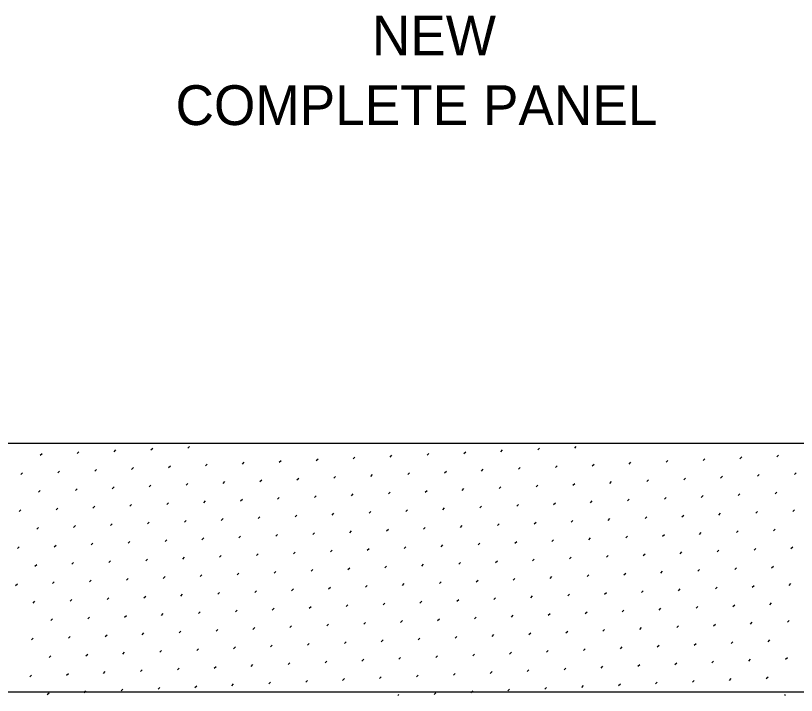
# Model space of a CAD drawing. Extents: x 49991.4 to 50021, y 49987.6 to 50011.4.
# Drawn here: x 50006.156 to 50007.726, y 49994.284 to 49995.65 of the extents above; entities that cross this region are included whole.
import ezdxf

# ---------------------------------------------------------------- set-up
doc = ezdxf.new("R2010")
doc.units = 0
for name, color, linetype in [('Level 1', 7, 'Continuous'), ('Level 10', 7, 'Continuous'), ('Level 2', 7, 'Continuous')]:
    doc.layers.add(name, color=color, linetype=linetype)

msp = doc.modelspace()

# ---------------------------------------------------------------- linework, layer by layer
at = {"layer": 'Level 1'}
for p, q in [((50007.9348, 49994.7903), (50002.3098, 49994.7903)), ((50015.1301, 49994.2903), (50001.3364, 49994.2903))]:
    msp.add_line(p, q, dxfattribs=at)
at = {"layer": 'Level 10'}
for p, q in [((50006.3541, 49994.7736), (50006.3576, 49994.7771)), ((50006.4283, 49994.7771), (50006.4319, 49994.7806)), ((50006.5026, 49994.7806), (50006.5058, 49994.7838)), ((50007.132, 49994.7736), (50007.1355, 49994.7772)), ((50007.2062, 49994.7772), (50007.2097, 49994.7807)), ((50007.2805, 49994.7807), (50007.2836, 49994.7838)), ((50006.2056, 49994.7665), (50006.2091, 49994.77)), ((50006.2798, 49994.77), (50006.2834, 49994.7735)), ((50006.8349, 49994.7595), (50006.8385, 49994.763)), ((50006.9092, 49994.763), (50006.9127, 49994.7665)), ((50006.9835, 49994.7665), (50006.987, 49994.7701)), ((50007.0577, 49994.7701), (50007.0612, 49994.7736)), ((50007.6128, 49994.7595), (50007.6164, 49994.7631)), ((50007.6871, 49994.7631), (50007.6906, 49994.7666)), ((50006.4637, 49994.7417), (50006.4672, 49994.7453)), ((50006.5379, 49994.7453), (50006.5415, 49994.7488)), ((50006.6122, 49994.7488), (50006.6157, 49994.7524)), ((50006.6864, 49994.7524), (50006.69, 49994.7559)), ((50006.7607, 49994.7559), (50006.7642, 49994.7594)), ((50007.2416, 49994.7418), (50007.2451, 49994.7453)), ((50007.3158, 49994.7454), (50007.3194, 49994.7489)), ((50007.3901, 49994.7489), (50007.3936, 49994.7524)), ((50007.4643, 49994.7524), (50007.4679, 49994.756)), ((50007.5386, 49994.756), (50007.5421, 49994.7595)), ((50006.1667, 49994.7276), (50006.1702, 49994.7311)), ((50006.2409, 49994.7311), (50006.2445, 49994.7347)), ((50006.3152, 49994.7347), (50006.3187, 49994.7382)), ((50006.3894, 49994.7382), (50006.393, 49994.7417)), ((50006.9446, 49994.7276), (50006.9481, 49994.7312)), ((50007.0188, 49994.7312), (50007.0223, 49994.7347)), ((50007.0931, 49994.7347), (50007.0966, 49994.7383)), ((50007.1673, 49994.7383), (50007.1709, 49994.7418)), ((50007.7224, 49994.7277), (50007.726, 49994.7312)), ((50006.5733, 49994.7099), (50006.5768, 49994.7135)), ((50006.6475, 49994.7135), (50006.6511, 49994.717)), ((50006.7218, 49994.717), (50006.7253, 49994.7206)), ((50006.796, 49994.7206), (50006.7996, 49994.7241)), ((50006.8703, 49994.7241), (50006.8738, 49994.7276)), ((50007.3512, 49994.71), (50007.3547, 49994.7135)), ((50007.4254, 49994.7135), (50007.429, 49994.7171)), ((50007.4997, 49994.7171), (50007.5032, 49994.7206)), ((50007.5739, 49994.7206), (50007.5775, 49994.7242)), ((50007.6482, 49994.7242), (50007.6517, 49994.7277)), ((50006.2763, 49994.6958), (50006.2798, 49994.6993)), ((50006.3505, 49994.6993), (50006.3541, 49994.7028)), ((50006.4248, 49994.7028), (50006.4283, 49994.7064)), ((50006.499, 49994.7064), (50006.5026, 49994.7099)), ((50007.0542, 49994.6958), (50007.0577, 49994.6994)), ((50007.1284, 49994.6994), (50007.132, 49994.7029)), ((50007.2027, 49994.7029), (50007.2062, 49994.7065)), ((50007.2769, 49994.7065), (50007.2805, 49994.71)), ((50006.202, 49994.6922), (50006.2056, 49994.6958)), ((50006.6829, 49994.6781), (50006.6864, 49994.6817)), ((50006.7572, 49994.6817), (50006.7607, 49994.6852)), ((50006.8314, 49994.6852), (50006.8349, 49994.6887)), ((50006.9057, 49994.6887), (50006.9092, 49994.6923)), ((50006.9799, 49994.6923), (50006.9834, 49994.6958)), ((50007.4608, 49994.6782), (50007.4643, 49994.6817)), ((50007.535, 49994.6817), (50007.5386, 49994.6853)), ((50007.6093, 49994.6853), (50007.6128, 49994.6888)), ((50007.6835, 49994.6888), (50007.6871, 49994.6924)), ((50006.3859, 49994.6639), (50006.3894, 49994.6675)), ((50006.4601, 49994.6675), (50006.4637, 49994.671)), ((50006.5344, 49994.671), (50006.5379, 49994.6746)), ((50006.6086, 49994.6746), (50006.6122, 49994.6781)), ((50007.1638, 49994.664), (50007.1673, 49994.6676)), ((50007.238, 49994.6676), (50007.2416, 49994.6711)), ((50007.3123, 49994.6711), (50007.3158, 49994.6746)), ((50007.3865, 49994.6746), (50007.3901, 49994.6782)), ((50006.1631, 49994.6533), (50006.1667, 49994.6569)), ((50006.2374, 49994.6569), (50006.2409, 49994.6604)), ((50006.3116, 49994.6604), (50006.3152, 49994.6639)), ((50006.8668, 49994.6498), (50006.8703, 49994.6534)), ((50006.941, 49994.6534), (50006.9445, 49994.6569)), ((50007.0153, 49994.6569), (50007.0188, 49994.6605)), ((50007.0895, 49994.6605), (50007.0931, 49994.664)), ((50007.6446, 49994.6499), (50007.6482, 49994.6535)), ((50007.7189, 49994.6535), (50007.7224, 49994.657)), ((50006.4955, 49994.6321), (50006.499, 49994.6357)), ((50006.5697, 49994.6357), (50006.5733, 49994.6392)), ((50006.644, 49994.6392), (50006.6475, 49994.6428)), ((50006.7183, 49994.6428), (50006.7218, 49994.6463)), ((50006.7925, 49994.6463), (50006.796, 49994.6498)), ((50007.2734, 49994.6322), (50007.2769, 49994.6357)), ((50007.3476, 49994.6357), (50007.3512, 49994.6393)), ((50007.4219, 49994.6393), (50007.4254, 49994.6428)), ((50007.4961, 49994.6428), (50007.4997, 49994.6464)), ((50007.5704, 49994.6464), (50007.5739, 49994.6499)), ((50006.1985, 49994.618), (50006.202, 49994.6215)), ((50006.2727, 49994.6215), (50006.2763, 49994.625)), ((50006.347, 49994.625), (50006.3505, 49994.6286)), ((50006.4212, 49994.6286), (50006.4248, 49994.6321)), ((50006.9764, 49994.618), (50006.9799, 49994.6216)), ((50007.0506, 49994.6216), (50007.0542, 49994.6251)), ((50007.1249, 49994.6251), (50007.1284, 49994.6287)), ((50007.1991, 49994.6287), (50007.2027, 49994.6322)), ((50006.6051, 49994.6003), (50006.6086, 49994.6039)), ((50006.6794, 49994.6039), (50006.6829, 49994.6074)), ((50006.7536, 49994.6074), (50006.7571, 49994.6109)), ((50006.8279, 49994.6109), (50006.8314, 49994.6145)), ((50006.9021, 49994.6145), (50006.9057, 49994.618)), ((50007.383, 49994.6004), (50007.3865, 49994.6039)), ((50007.4572, 49994.6039), (50007.4608, 49994.6075)), ((50007.5315, 49994.6075), (50007.535, 49994.611)), ((50007.6057, 49994.611), (50007.6093, 49994.6146)), ((50007.68, 49994.6146), (50007.6835, 49994.6181)), ((50006.3081, 49994.5862), (50006.3116, 49994.5897)), ((50006.3823, 49994.5897), (50006.3859, 49994.5932)), ((50006.4566, 49994.5932), (50006.4601, 49994.5968)), ((50006.5308, 49994.5968), (50006.5344, 49994.6003)), ((50007.086, 49994.5862), (50007.0895, 49994.5898)), ((50007.1602, 49994.5898), (50007.1638, 49994.5933)), ((50007.2345, 49994.5933), (50007.238, 49994.5968)), ((50007.3087, 49994.5968), (50007.3123, 49994.6004)), ((50006.1596, 49994.5791), (50006.1631, 49994.5826)), ((50006.2338, 49994.5826), (50006.2374, 49994.5861)), ((50006.7147, 49994.5685), (50006.7182, 49994.572)), ((50006.789, 49994.5721), (50006.7925, 49994.5756)), ((50006.8632, 49994.5756), (50006.8668, 49994.5791)), ((50006.9375, 49994.5791), (50006.941, 49994.5827)), ((50007.0117, 49994.5827), (50007.0153, 49994.5862)), ((50007.4926, 49994.5686), (50007.4961, 49994.5721)), ((50007.5669, 49994.5721), (50007.5704, 49994.5757)), ((50007.6411, 49994.5757), (50007.6446, 49994.5792)), ((50007.7154, 49994.5792), (50007.7189, 49994.5827)), ((50006.4177, 49994.5543), (50006.4212, 49994.5579)), ((50006.492, 49994.5579), (50006.4955, 49994.5614)), ((50006.5662, 49994.5614), (50006.5697, 49994.565)), ((50006.6405, 49994.565), (50006.644, 49994.5685)), ((50007.1956, 49994.5544), (50007.1991, 49994.5579)), ((50007.2698, 49994.558), (50007.2734, 49994.5615)), ((50007.3441, 49994.5615), (50007.3476, 49994.565)), ((50007.4183, 49994.565), (50007.4219, 49994.5686)), ((50006.1949, 49994.5437), (50006.1985, 49994.5472)), ((50006.2692, 49994.5473), (50006.2727, 49994.5508)), ((50006.3434, 49994.5508), (50006.347, 49994.5543)), ((50006.8986, 49994.5402), (50006.9021, 49994.5438)), ((50006.9728, 49994.5438), (50006.9764, 49994.5473)), ((50007.0471, 49994.5473), (50007.0506, 49994.5509)), ((50007.1213, 49994.5509), (50007.1249, 49994.5544)), ((50007.6765, 49994.5403), (50007.68, 49994.5438)), ((50006.5273, 49994.5225), (50006.5308, 49994.5261)), ((50006.6016, 49994.5261), (50006.6051, 49994.5296)), ((50006.6758, 49994.5296), (50006.6793, 49994.5331)), ((50006.7501, 49994.5332), (50006.7536, 49994.5367)), ((50006.8243, 49994.5367), (50006.8279, 49994.5402)), ((50007.3052, 49994.5226), (50007.3087, 49994.5261)), ((50007.3794, 49994.5261), (50007.383, 49994.5297)), ((50007.4537, 49994.5297), (50007.4572, 49994.5332)), ((50007.528, 49994.5332), (50007.5315, 49994.5368)), ((50007.6022, 49994.5368), (50007.6057, 49994.5403)), ((50006.2303, 49994.5084), (50006.2338, 49994.5119)), ((50006.3045, 49994.5119), (50006.3081, 49994.5154)), ((50006.3788, 49994.5154), (50006.3823, 49994.519)), ((50006.4531, 49994.519), (50006.4566, 49994.5225)), ((50007.0082, 49994.5084), (50007.0117, 49994.512)), ((50007.0824, 49994.512), (50007.086, 49994.5155)), ((50007.1567, 49994.5155), (50007.1602, 49994.519)), ((50007.2309, 49994.5191), (50007.2345, 49994.5226)), ((50006.156, 49994.5048), (50006.1596, 49994.5083)), ((50006.6369, 49994.4907), (50006.6404, 49994.4942)), ((50006.7112, 49994.4943), (50006.7147, 49994.4978)), ((50006.7854, 49994.4978), (50006.789, 49994.5013)), ((50006.8597, 49994.5013), (50006.8632, 49994.5049)), ((50006.9339, 49994.5049), (50006.9375, 49994.5084)), ((50007.4148, 49994.4908), (50007.4183, 49994.4943)), ((50007.4891, 49994.4943), (50007.4926, 49994.4979)), ((50007.5633, 49994.4979), (50007.5668, 49994.5014)), ((50007.6376, 49994.5014), (50007.6411, 49994.5049)), ((50007.7118, 49994.505), (50007.7154, 49994.5085)), ((50006.3399, 49994.4765), (50006.3434, 49994.4801)), ((50006.4142, 49994.4801), (50006.4177, 49994.4836)), ((50006.4884, 49994.4836), (50006.4919, 49994.4872)), ((50006.5627, 49994.4872), (50006.5662, 49994.4907)), ((50007.1178, 49994.4766), (50007.1213, 49994.4801)), ((50007.192, 49994.4802), (50007.1956, 49994.4837)), ((50007.2663, 49994.4837), (50007.2698, 49994.4872)), ((50007.3405, 49994.4872), (50007.3441, 49994.4908)), ((50006.1914, 49994.4695), (50006.1949, 49994.473)), ((50006.2656, 49994.473), (50006.2692, 49994.4765)), ((50006.7465, 49994.4589), (50006.7501, 49994.4624)), ((50006.8208, 49994.4624), (50006.8243, 49994.466)), ((50006.895, 49994.466), (50006.8986, 49994.4695)), ((50006.9693, 49994.4695), (50006.9728, 49994.4731)), ((50007.0435, 49994.4731), (50007.0471, 49994.4766)), ((50007.5244, 49994.459), (50007.5279, 49994.4625)), ((50007.5987, 49994.4625), (50007.6022, 49994.466)), ((50007.6729, 49994.4661), (50007.6765, 49994.4696)), ((50006.4495, 49994.4447), (50006.453, 49994.4483)), ((50006.5238, 49994.4483), (50006.5273, 49994.4518)), ((50006.598, 49994.4518), (50006.6016, 49994.4554)), ((50006.6723, 49994.4554), (50006.6758, 49994.4589)), ((50007.2274, 49994.4448), (50007.2309, 49994.4483)), ((50007.3017, 49994.4483), (50007.3052, 49994.4519)), ((50007.3759, 49994.4519), (50007.3794, 49994.4554)), ((50007.4502, 49994.4554), (50007.4537, 49994.459)), ((50006.2268, 49994.4341), (50006.2303, 49994.4376)), ((50006.301, 49994.4376), (50006.3045, 49994.4412)), ((50006.3753, 49994.4412), (50006.3788, 49994.4447)), ((50006.8561, 49994.4271), (50006.8597, 49994.4306)), ((50006.9304, 49994.4306), (50006.9339, 49994.4342)), ((50007.0046, 49994.4342), (50007.0082, 49994.4377)), ((50007.0789, 49994.4377), (50007.0824, 49994.4413)), ((50007.1531, 49994.4413), (50007.1567, 49994.4448)), ((50007.634, 49994.4272), (50007.6376, 49994.4307)), ((50007.7083, 49994.4307), (50007.7118, 49994.4342)), ((50006.5591, 49994.4129), (50006.5627, 49994.4165)), ((50006.6334, 49994.4165), (50006.6369, 49994.42)), ((50006.7076, 49994.42), (50006.7112, 49994.4235)), ((50006.7819, 49994.4235), (50006.7854, 49994.4271)), ((50007.337, 49994.413), (50007.3405, 49994.4165)), ((50007.4113, 49994.4165), (50007.4148, 49994.4201)), ((50007.4855, 49994.4201), (50007.489, 49994.4236)), ((50007.5598, 49994.4236), (50007.5633, 49994.4272)), ((50006.2621, 49994.3987), (50006.2656, 49994.4023)), ((50006.3364, 49994.4023), (50006.3399, 49994.4058)), ((50006.4106, 49994.4058), (50006.4141, 49994.4094)), ((50006.4849, 49994.4094), (50006.4884, 49994.4129)), ((50007.04, 49994.3988), (50007.0435, 49994.4024)), ((50007.1142, 49994.4024), (50007.1178, 49994.4059)), ((50007.1885, 49994.4059), (50007.192, 49994.4094)), ((50007.2628, 49994.4094), (50007.2663, 49994.413)), ((50006.1879, 49994.3952), (50006.1914, 49994.3987)), ((50006.6687, 49994.3811), (50006.6723, 49994.3846)), ((50006.743, 49994.3846), (50006.7465, 49994.3882)), ((50006.8172, 49994.3882), (50006.8208, 49994.3917)), ((50006.8915, 49994.3917), (50006.895, 49994.3953)), ((50006.9657, 49994.3953), (50006.9693, 49994.3988)), ((50007.4466, 49994.3812), (50007.4502, 49994.3847)), ((50007.5209, 49994.3847), (50007.5244, 49994.3883)), ((50007.5951, 49994.3883), (50007.5987, 49994.3918)), ((50007.6694, 49994.3918), (50007.6729, 49994.3953)), ((50006.3717, 49994.3669), (50006.3752, 49994.3705)), ((50006.446, 49994.3705), (50006.4495, 49994.374)), ((50006.5202, 49994.374), (50006.5238, 49994.3776)), ((50006.5945, 49994.3776), (50006.598, 49994.3811)), ((50007.1496, 49994.367), (50007.1531, 49994.3705)), ((50007.2239, 49994.3705), (50007.2274, 49994.3741)), ((50007.2981, 49994.3741), (50007.3016, 49994.3776)), ((50007.3724, 49994.3776), (50007.3759, 49994.3812)), ((50006.2232, 49994.3598), (50006.2267, 49994.3634)), ((50006.2975, 49994.3634), (50006.301, 49994.3669)), ((50006.7783, 49994.3493), (50006.7819, 49994.3528)), ((50006.8526, 49994.3528), (50006.8561, 49994.3564)), ((50006.9268, 49994.3564), (50006.9304, 49994.3599)), ((50007.0011, 49994.3599), (50007.0046, 49994.3635)), ((50007.0753, 49994.3635), (50007.0789, 49994.367)), ((50007.5562, 49994.3494), (50007.5598, 49994.3529)), ((50007.6305, 49994.3529), (50007.634, 49994.3564)), ((50007.7047, 49994.3564), (50007.7083, 49994.36)), ((50006.4813, 49994.3351), (50006.4849, 49994.3387)), ((50006.5556, 49994.3387), (50006.5591, 49994.3422)), ((50006.6298, 49994.3422), (50006.6334, 49994.3457)), ((50006.7041, 49994.3457), (50006.7076, 49994.3493)), ((50007.2592, 49994.3352), (50007.2627, 49994.3387)), ((50007.3335, 49994.3387), (50007.337, 49994.3423)), ((50007.4077, 49994.3423), (50007.4113, 49994.3458)), ((50007.482, 49994.3458), (50007.4855, 49994.3494)), ((50006.1843, 49994.321), (50006.1878, 49994.3245)), ((50006.2586, 49994.3245), (50006.2621, 49994.328)), ((50006.3328, 49994.328), (50006.3364, 49994.3316)), ((50006.4071, 49994.3316), (50006.4106, 49994.3351)), ((50006.8879, 49994.3175), (50006.8915, 49994.321)), ((50006.9622, 49994.321), (50006.9657, 49994.3246)), ((50007.0365, 49994.3246), (50007.04, 49994.3281)), ((50007.1107, 49994.3281), (50007.1142, 49994.3316)), ((50007.185, 49994.3316), (50007.1885, 49994.3352)), ((50007.6658, 49994.3175), (50007.6694, 49994.3211)), ((50006.5909, 49994.3033), (50006.5945, 49994.3068)), ((50006.6652, 49994.3069), (50006.6687, 49994.3104)), ((50006.7394, 49994.3104), (50006.743, 49994.3139)), ((50006.8137, 49994.3139), (50006.8172, 49994.3175)), ((50007.3688, 49994.3034), (50007.3724, 49994.3069)), ((50007.4431, 49994.3069), (50007.4466, 49994.3105)), ((50007.5173, 49994.3105), (50007.5209, 49994.314)), ((50007.5916, 49994.314), (50007.5951, 49994.3175)), ((50006.2197, 49994.2856), (50006.2232, 49994.2891)), ((50006.2939, 49994.2891), (50006.2975, 49994.2927)), ((50006.3682, 49994.2927), (50006.3717, 49994.2962)), ((50006.4424, 49994.2962), (50006.446, 49994.2998)), ((50006.5167, 49994.2998), (50006.5202, 49994.3033)), ((50006.9976, 49994.2857), (50007.0011, 49994.2892)), ((50007.0718, 49994.2892), (50007.0753, 49994.2927)), ((50007.1461, 49994.2928), (50007.1496, 49994.2963)), ((50007.2203, 49994.2963), (50007.2238, 49994.2998)), ((50007.2946, 49994.2998), (50007.2981, 49994.3034)), ((50006.925, 49994.2838), (50006.9268, 49994.2857)), ((50007.7028, 49994.2838), (50007.7047, 49994.2857))]:
    msp.add_line(p, q, dxfattribs=at)

# ---------------------------------------------------------------- texts
at = {"layer": 'Level 2'}
for s, p in [('NEW', (50006.8725, 49995.5703)), ('COMPLETE PANEL', (50006.4777, 49995.4303))]:
    msp.add_text(s, height=0.08, dxfattribs=at).set_placement(p)

doc.saveas('drawing.dxf')
